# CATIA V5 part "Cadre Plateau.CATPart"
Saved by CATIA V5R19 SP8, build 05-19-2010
Part number: Cadre Plateau
Nomenclature: 5
Bounding box of the stored display mesh (mm): x -294 to 294, y -16.5 to 1531.981, z -105 to 81
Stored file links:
  C:\Users\rphgr\Desktop\0_Tapis_TC520B_vitesse\Cadre Plateau.CATPart
  C:\Program Files\Dassault Systemes\B19\win_b64\reffiles\standard\MetricThickPitch.txt
  D:\Documents\1_Travail\1 - ac-limoges.fr\ac-limoges.fr\Emmanuel Maynard - STI2D_Turgot\3 - Supports\Tapis de course TC520B\Tapis de course TC520B_Ca\0_Tapis_TC520B.CATProduct
  C:\Users\rphgr\Desktop\0_Tapis_TC520B_vitesse\Roulette_Plateau.CATPart
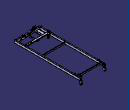
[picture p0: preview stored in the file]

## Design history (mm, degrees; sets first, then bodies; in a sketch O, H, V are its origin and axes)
AxisSystem1: origin (0, 0, 0), X (1, 0, 0), Y (0, 1, 0), Z (0, 0, 1)
Set1
  DatumCurve1: linked copy from another document
Set2
  Sketch1 on YZ plane of AxisSystem1, origin (0, 0, 0), H (0, 1, 0), V (0, 0, 1)
    projected circle E1 centre (1514.5, -85) radius 27.5 from edge of DatumCurve1
Body1 "Cadre" (main body)
  Sketch2 on YZ plane of AxisSystem1, origin (0, 0, 0), H (0, 1, 0), V (0, 0, 1)
    line L1 (12.5, 23.5) -> (12.5, -23.5)
    line L2 (11, -25) -> (-11, -25)
    line L3 (-12.5, -23.5) -> (-12.5, 23.5)
    line L4 (-11, 25) -> (11, 25)
    arc A1 centre (-11, 23.5) radius 1.5 from (-12.5, 23.5) to (-11, 25) cw
    arc A2 centre (11, 23.5) radius 1.5 from (12.5, 23.5) to (11, 25) ccw
    arc A3 centre (11, -23.5) radius 1.5 from (12.5, -23.5) to (11, -25) cw
    arc A4 centre (-11, -23.5) radius 1.5 from (-11, -25) to (-12.5, -23.5) cw
    distance L1 L3 = 25
    distance L4 L2 = 50
    radius A1 = 1.5
    radius A2 = 1.5
    radius A3 = 1.5
    radius A4 = 1.5
    vertical: L1 V, L3 V
    horizontal: L2 H, L4 H
    equidistance: L1 L3 O, L2 L4 O
    tangency: A1 L3, A1 L4, A2 L1, A2 L4, A3 L1, A3 L2, A4 L2, A4 L3
  Pad1: profile Sketch2, direction (1, 0, 0), length 269, mirrored extent, thin wall 1.5
  Sketch3 on ZX plane of AxisSystem1, origin (0, 0, 0), H (0, 0, 1), V (1, 0, 0)
    point P1 (0, 281.5)
    line L1 (25, 292.5) -> (25, 270.5)
    line L2 (23.5, 269) -> (-23.5, 269)
    line L3 (-25, 270.5) -> (-25, 292.5)
    line L4 (-23.5, 294) -> (23.5, 294)
    point P2 (0, -281.5)
    line L5 (25, -270.5) -> (25, -292.5)
    line L6 (23.5, -294) -> (-23.5, -294)
    line L7 (-25, -292.5) -> (-25, -270.5)
    line L8 (-23.5, -269) -> (23.5, -269)
    reference intersected line E1 through (0, 269) direction (-1, 0) from end face of Pad1
    reference intersected line E2 through (0, -269) direction (-1, 0) from start face of Pad1
    reference intersected line E3 (25, 269) -> (25, -269) from face of Pad1
    arc A1 centre (-23.5, -270.5) radius 1.5 from (-25, -270.5) to (-23.5, -269) cw
    arc A2 centre (23.5, -270.5) radius 1.5 from (25, -270.5) to (23.5, -269) ccw
    arc A3 centre (23.5, -292.5) radius 1.5 from (25, -292.5) to (23.5, -294) cw
    arc A4 centre (-23.5, -292.5) radius 1.5 from (-23.5, -294) to (-25, -292.5) cw
    arc A5 centre (-23.5, 292.5) radius 1.5 from (-25, 292.5) to (-23.5, 294) cw
    arc A6 centre (-23.5, 270.5) radius 1.5 from (-23.5, 269) to (-25, 270.5) cw
    arc A7 centre (23.5, 270.5) radius 1.5 from (25, 270.5) to (23.5, 269) cw
    arc A8 centre (23.5, 292.5) radius 1.5 from (25, 292.5) to (23.5, 294) ccw
    distance L4 L2 = 25
    distance L8 L6 = 25
    radius A1 = 1.5
    radius A2 = 1.5
    radius A3 = 1.5
    radius A4 = 1.5
    radius A5 = 1.5
    radius A6 = 1.5
    radius A7 = 1.5
    radius A8 = 1.5
    coincidence: P1 V, P2 V, L1 L5, L2 E1, L8 E2, L1 E3
    vertical: L1 V, L3 V, L5 V, L7 V
    horizontal: L2 H, L4 H, L6 H, L8 H
    equidistance: L1 L3 P1, L2 L4 P1, L5 L7 P2, L6 L8 P2
    tangency: A1 L7, A1 L8, A2 L5, A2 L8, A3 L5, A3 L6, A4 L6, A4 L7, A5 L3, A5 L4, A6 L2, A6 L3, A7 L1, A7 L2, A8 L1, A8 L4
  Pad2: profile Sketch3, direction (0, -1, 0), up to face of Pad1, offset 4, opposite side length 1516.5, thin wall 1.5
  Sketch4 on face of Pad2, origin (-269, 0, 0), H (0, 1, 0), V (0, 0, 1)
    line L1 (179, 3) -> (216, 3)
    line L2 (217.5, 1.5) -> (217.5, -15.5)
    line L3 (216, -17) -> (179, -17)
    line L4 (177.5, -15.5) -> (177.5, 1.5)
    line L5 (589, 10.5) -> (601, 10.5)
    line L6 (602.5, 9) -> (602.5, -18)
    line L7 (601, -19.5) -> (589, -19.5)
    line L8 (587.5, -18) -> (587.5, 9)
    line L9 (1415.1994, 19) -> (1426.8759, 19)
    line L10 (1429, 16.8759) -> (1429, -9.2652)
    line L11 (1427.2652, -11) -> (1415.8517, -11)
    line L12 (1414, -9.1483) -> (1414, 17.8006)
    arc A1 centre (179, -15.5) radius 1.5 from (179, -17) to (177.5, -15.5) cw
    arc A2 centre (179, 1.5) radius 1.5 from (179, 3) to (177.5, 1.5) ccw
    arc A3 centre (216, 1.5) radius 1.5 from (216, 3) to (217.5, 1.5) cw
    arc A4 centre (216, -15.5) radius 1.5 from (217.5, -15.5) to (216, -17) cw
    reference intersected line E1 (12.5, 23.5) -> (12.5, -23.5) from face of Pad1
    reference intersected line E2 through (0, 25) direction (1, 0) from face of Pad2
    arc A5 centre (589, 9) radius 1.5 from (589, 10.5) to (587.5, 9) ccw
    arc A6 centre (601, 9) radius 1.5 from (601, 10.5) to (602.5, 9) cw
    arc A7 centre (601, -18) radius 1.5 from (602.5, -18) to (601, -19.5) cw
    arc A8 centre (589, -18) radius 1.5 from (589, -19.5) to (587.5, -18) cw
    reference intersected line E3 through (0, 25) direction (1, 0) from face of Pad2
    arc A9 centre (1415.1994, 17.8006) radius 1.1994 from (1415.1994, 19) to (1414, 17.8006) ccw
    arc A10 centre (1426.8759, 16.8759) radius 2.1241 from (1426.8759, 19) to (1429, 16.8759) cw
    arc A11 centre (1415.8517, -9.1483) radius 1.8517 from (1415.8517, -11) to (1414, -9.1483) cw
    arc A12 centre (1427.2652, -9.2652) radius 1.7348 from (1429, -9.2652) to (1427.2652, -11) cw
    reference intersected line E4 through (0, 25) direction (1, 0) from face of Pad2
    reference intersected line E5 (1516.5, 23.5) -> (1516.5, -23.5) from start face of Pad2
    distance L1 L3 = 20
    distance L2 L4 = 40
    radius A1 = 1.5
    radius A2 = 1.5
    radius A3 = 1.5
    radius A4 = 1.5
    distance L4 E1 = 165
    distance L1 E2 = 22
    radius A5 = 1.5
    radius A6 = 1.5
    radius A7 = 1.5
    radius A8 = 1.5
    distance L8 L6 = 15
    distance L7 L5 = 30
    distance L8 L2 = 370
    distance L5 E3 = 14.5
    radius A9 = 1.1994
    radius A10 = 2.1241
    radius A11 = 1.8517
    radius A12 = 1.7348
    distance L12 L10 = 15
    distance L11 L9 = 30
    distance L9 E4 = 6
    distance L10 E5 = 87.5
    horizontal: L1 H, L3 H, L5 H, L7 H, L9 H, L11 H
    vertical: L2 V, L4 V, L6 V, L8 V, L10 V, L12 V
    tangency: A1 L3, A1 L4, A2 L1, A2 L4, A3 L1, A3 L2, A4 L2, A4 L3, A5 L5, A5 L8, A6 L5, A6 L6, A7 L6, A7 L7, A8 L7, A8 L8, A9 L9, A9 L12, A10 L9, A10 L10, A11 L11, A11 L12, A12 L10, A12 L11
  Pad3: profile Sketch4, direction (1, 0, 0), up to the existing solid (limit type 2), thin wall 1.5
  Sketch5 on face of Pad3, origin (0, 0, 3), H (1, 0, 0), V (0, 1, 0)
    circle A1 centre (163.8401, 188.5) radius 4.5
    point P1 (163.8401, 188.5)
    circle A2 centre (93.8401, 188.5) radius 4.5
    point P2 (93.8401, 188.5)
    reference intersected line E1 through (0, 217.5) direction (-1, 0) from face of Pad3
    reference intersected line E2 through (0, 217.5) direction (-1, 0) from face of Pad3
    reference projected point E3 (163.8401, 32.5) from axis of face of Hole10
    radius A2 = 4.5
    radius A1 = 4.5
    distance P2 P1 = 70
    distance P1 E1 = 29
    distance P2 E2 = 29
    distance P1 E3 H = 0
  Pocket1: profile Sketch5, direction (0, 0, -1), through (limit type 3)
  Sketch6 on face of Pad2, origin (-281.5, 304.8043, 25), H (1, 0, 0), V (0, 1, 0)
    point P1 (2.5, 18.6957)
    reference intersected line E1 through (-12.5, 0) direction (0, -1) from face of Pad2
    reference intersected line E2 through (0, -321.3043) direction (-1, 0) from end face of Pad2
    distance P1 E1 = 15
    distance P1 E2 = 340
  Hole1: placed by Sketch6, at (-279, 323.5, 25) direction (0, 0, -1), diameter 4.917, depth 5, threaded "M6", thread diameter 6, thread depth 5, pitch 1
  Sketch7 on face of Pad2, origin (-279, 673.206, 25), H (1, 0, 0), V (0, 1, 0)
    point P1 (0, -2.206)
    reference intersected line E1 through (-15, 0) direction (0, -1) from face of Pad2
    reference projected point E2 (0, -349.706) from axis of face of Hole1
    distance P1 E1 = 15
    distance P1 E2 = 347.5
  Hole2: placed by Sketch7, at (-279, 671, 25) direction (0, 0, -1), diameter 4.917, depth 5, threaded "M6", thread diameter 6, thread depth 5, pitch 1
  Sketch8 on face of Pad2, origin (-280.7836, 1023.4299, 25), H (1, 0, 0), V (0, 1, 0)
    point P1 (1.7836, 2.5701)
    reference intersected line E1 through (-13.2164, 0) direction (0, -1) from face of Pad2
    reference projected point E2 (1.7836, -352.4299) from axis of face of Hole2
    distance P1 E1 = 15
    distance P1 E2 = 355
  Hole3: placed by Sketch8, at (-279, 1026, 25) direction (0, 0, -1), diameter 4.917, depth 5, threaded "M6", thread diameter 6, thread depth 5, pitch 1
  Mirror1: of Hole1, Hole2, Hole3, about YZ plane of AxisSystem1
  Plane1: type Offset, RefPlane end face of Pad2, Offset 39
  Sketch9 on Plane1, origin (0, 22.5, 0), H (-1, 0, 0), V (0, 0, 1)
    point P1 (294, 43)
    line L1 (294, 43) -> (294, 28)
    arc A1 centre (291, 28) radius 3 from (294, 28) to (291, 25) cw
    line L2 (291, 25) -> (279, 25)
    point P5 (279, 25)
    reference intersected line E1 (270.5, 25) -> (292.5, 25) from face of Pad2
    reference intersected line E2 (294, 23.5) -> (294, -23.5) from face of Pad2
    radius A1 = 3
    distance P1 L2 = 18
    distance P5 L1 = 15
    vertical: L1 V
    tangency: A1 L1, A1 L2
    horizontal: L2 H
    coincidence: L2 E1, L1 E2
  Pad4: profile Sketch9, direction (0, 1, 0), length 219, thin wall 2
  Sketch10 on face of Pad4, origin (-294, 0, 0), H (0, -1, 0), V (0, 0, 1)
    line L1 (-221.5, 43) -> (-42.5, 43)
    line L2 (-42.5, 43) -> (-42.5, 25)
    line L3 (-42.5, 25) -> (-221.5, 25)
    line L4 (-221.5, 25) -> (-221.5, 43)
    reference intersected line E1 through (0, 25) direction (1, 0) from face of Pad2
    reference intersected line E2 (-241.5, 43) -> (-22.5, 43) from face of Pad4
    reference intersected line E3 (-22.5, 43) -> (-22.5, 28) from start face of Pad4
    reference intersected line E4 (-241.5, 28) -> (-241.5, 43) from end face of Pad4
    distance L2 E3 = 20
    distance L4 E4 = 20
    horizontal: L1 H, L3 H
    vertical: L2 V, L4 V
    coincidence: L3 E1, L1 E2
  Pocket2: profile Sketch10, direction (1, 0, 0), through (limit type 6)
  Sketch11 on face of Pad4, origin (-294, 32.5, 35.5), H (0, 1, 0), V (0, 0, -1)
    point P1 (0, 0.5)
    reference intersected line E1 (10, -7.5) -> (10, 7.5) from face of Pocket2 from Sketch10.L2
    reference intersected line E2 through (0, 10.5) direction (-1, 0) from face of Pad2
    distance P1 E1 = 10
    distance P1 E2 = 10
  Hole4: placed by Sketch11, at (-294, 32.5, 35) direction (1, 0, 0), diameter 3.242, depth 5, threaded "M4", thread diameter 4, thread depth 5, pitch 0.7
  Sketch12 on face of Pad4, origin (-294, 232.5037, 35.5), H (0, 1, 0), V (0, 0, -1)
    point P1 (-1.0037, 0.5)
    reference intersected line E1 (8.9963, 7.5) -> (8.9963, -7.5) from end face of Pad4
    reference intersected line E2 through (0, 10.5) direction (-1, 0) from face of Pad2
    distance P1 E1 = 10
    distance P1 E2 = 10
  Hole5: placed by Sketch12, at (-294, 231.5, 35) direction (1, 0, 0), diameter 3.242, depth 5, threaded "M4", thread diameter 4, thread depth 5, pitch 0.7
  Fillet1: radius 3, on edge [face of Pad4 | end face of Pad4]; edge [face of Pocket2 from Sketch10.L4 | face of Pad4]; edge [face of Pad4 | face of Pocket2 from Sketch10.L2]; edge [start face of Pad4 | face of Pad4]
  Mirror2: of Pad4, Pocket2, Hole4, Hole5, Fillet1, about YZ plane of AxisSystem1
  Sketch13 on face of Pad2, origin (0, 0, -25), H (1, 0, 0), V (0, -1, 0)
    circle A1 centre (-281.5, -40.5) radius 1.75
    point P1 (-281.5, -40.5)
    circle A2 centre (-281.5, -190.5) radius 1.75
    point P2 (-281.5, -190.5)
    circle A3 centre (-281.5, -290.5) radius 1.75
    point P3 (-281.5, -290.5)
    reference intersected line E1 through (-294, 0) direction (0, -1) from face of Pad2
    reference intersected line E2 through (-294, 0) direction (0, -1) from face of Pad2
    reference intersected line E3 through (-294, 0) direction (0, -1) from face of Pad2
    reference intersected line E4 through (0, 16.5) direction (1, 0) from end face of Pad2
    radius A1 = 1.75
    radius A2 = 1.75
    radius A3 = 1.75
    distance P1 E1 = 12.5
    distance P2 E2 = 12.5
    distance P3 E3 = 12.5
    distance P1 E4 = 57
    distance P1 P2 = 150
    distance P2 P3 = 100
  Pocket3: profile Sketch13, direction (0, 0, 1), through (limit type 6)
  Mirror3: of Pocket3, about YZ plane of AxisSystem1
  Sketch14 on YZ plane of AxisSystem1, origin (0, 0, 0), H (0, 1, 0), V (0, 0, 1)
    point P1 (-12.5, 43)
    line L1 (-12.5, 43) -> (-12.5, 28)
    arc A1 centre (-9.5, 28) radius 3 from (-12.5, 28) to (-9.5, 25) ccw
    line L2 (-9.5, 25) -> (2.5, 25)
    point P5 (2.5, 25)
    reference intersected line E1 (-12.5, -23.5) -> (-12.5, 23.5) from face of Pad1
    reference intersected line E2 (-11, 25) -> (11, 25) from face of Pad1
    radius A1 = 3
    distance P1 L2 = 18
    distance P5 L1 = 15
    vertical: L1 V
    tangency: A1 L1, A1 L2
    horizontal: L2 H
    coincidence: L1 E1, L2 E2
  Pad5: profile Sketch14, direction (1, 0, 0), length 120, mirrored extent, thin wall 2
  Sketch15 on face of Pad5, origin (0, -12.5, 0), H (1, 0, 0), V (0, 0, 1)
    line L1 (-100, 43) -> (100, 43)
    line L2 (100, 43) -> (100, 25)
    line L3 (100, 25) -> (-100, 25)
    line L4 (-100, 25) -> (-100, 43)
    reference intersected line E1 (-120, 43) -> (120, 43) from face of Pad5
    reference intersected line E2 through (0, 25) direction (1, 0) from face of Pad1
    reference intersected line E3 (120, 43) -> (120, 28) from end face of Pad5
    reference intersected line E4 (-120, 28) -> (-120, 43) from start face of Pad5
    distance L2 E3 = 20
    distance L4 E4 = 20
    horizontal: L1 H, L3 H
    vertical: L2 V, L4 V
    coincidence: L1 E1, L3 E2
  Pocket4: profile Sketch15, direction (0, 1, 0), through (limit type 3)
  Fillet2: radius 3, on edge [start face of Pad5 | face of Pad5]; edge [face of Pocket4 from Sketch15.L4 | face of Pad5]; edge [face of Pad5 | face of Pocket4 from Sketch15.L2]; edge [face of Pad5 | end face of Pad5]
  Sketch16 on face of Pad5, origin (-110, -12.5, 35.5), H (1, 0, 0), V (0, 0, 1)
    point P1 (0, -0.5)
    reference intersected line E1 (-10, -7.5) -> (-10, 7.5) from start face of Pad5
    reference intersected line E2 through (0, -10.5) direction (1, 0) from face of Pad1
    distance P1 E1 = 10
    distance P1 E2 = 10
  Hole6: placed by Sketch16, at (-110, -12.5, 35) direction (0, 1, 0), diameter 3.242, depth 5, threaded "M4", thread diameter 4, thread depth 5, pitch 0.7
  Sketch17 on face of Pad5, origin (110, -12.5, 35.5), H (1, 0, 0), V (0, 0, 1)
    point P1 (0, -0.5)
    reference intersected line E1 (-10, 7.5) -> (-10, -7.5) from face of Pocket4 from Sketch15.L2
    reference intersected line E2 through (0, -10.5) direction (1, 0) from face of Pad1
    distance P1 E1 = 10
    distance P1 E2 = 10
  Hole7: placed by Sketch17, at (110, -12.5, 35) direction (0, 1, 0), diameter 3.242, depth 5, threaded "M4", thread diameter 4, thread depth 5, pitch 0.7
  Sketch18 on face of Pad3, origin (0, 177.5, 0), H (1, 0, 0), V (0, 0, 1)
    line L1 (1.5, 6) -> (11.5, 6)
    line L2 (13, 4.5) -> (13, -18.5)
    line L3 (11.5, -20) -> (1.5, -20)
    line L4 (0, -18.5) -> (0, 4.5)
    arc A1 centre (1.5, 4.5) radius 1.5 from (1.5, 6) to (0, 4.5) ccw
    arc A2 centre (11.5, 4.5) radius 1.5 from (13, 4.5) to (11.5, 6) ccw
    arc A3 centre (11.5, -18.5) radius 1.5 from (13, -18.5) to (11.5, -20) cw
    arc A4 centre (1.5, -18.5) radius 1.5 from (1.5, -20) to (0, -18.5) cw
    reference intersected line E1 through (0, 3) direction (1, 0) from face of Pad3
    reference intersected line E2 (269, -23.5) -> (269, 23.5) from face of Pad2
    radius A1 = 1.5
    radius A2 = 1.5
    radius A3 = 1.5
    radius A4 = 1.5
    distance L2 L4 = 13
    distance L3 L1 = 26
    distance L1 E1 = 3
    distance E2 L2 = 256
    horizontal: L1 H, L3 H
    vertical: L2 V, L4 V
    tangency: A1 L1, A1 L4, A2 L2, A2 L1, A3 L2, A3 L3, A4 L3, A4 L4
  Pad6: profile Sketch18, direction (0, -1, 0), up to face of Pad1
  Plane2: type Offset, RefPlane YZ plane of AxisSystem1, Offset 17, reversed
  Sketch19 on Plane2, origin (-17, 0, 0), H (0, 1, 0), V (0, 0, 1)
    line L1 (12.5, 25) -> (-7.5, 25)
    line L2 (-7.5, 25) -> (-7.5, 31)
    arc A1 centre (42.5, 31) radius 50 from (-7.5, 31) to (42.5, 81) cw
    point P5 (42.5, 81)
    construction line L3 (57.5, 66) -> (44.5614, 66)
    point P6 (57.5, 66)
    line L4 (57.5, 51) -> (47.5, 51)
    line L5 (42.5, 81) -> (57.5, 81)
    arc A2 centre (57.5, 66) radius 15 from (57.5, 81) to (57.5, 51) cw
    point P9 (42.5, 81)
    line L6 (12.5, 25) -> (12.5, -25)
    line L7 (12.5, -25) -> (27.5, -25)
    line L8 (27.5, -25) -> (27.5, 31)
    arc A3 centre (47.5, 31) radius 20 from (27.5, 31) to (47.5, 51) cw
    reference intersected line E1 (-11, 25) -> (11, 25) from face of Pad1
    reference intersected line E2 (12.5, 23.5) -> (12.5, -23.5) from face of Pad1
    reference intersected line E3 (11, -25) -> (-11, -25) from face of Pad1
    circle A4 centre (57.5, 66) radius 5.2
    distance L3 L4 = 15
    distance L2 L8 = 35
    distance L2 L6 = 20
    distance P6 L6 = 45
    distance L1 L3 = 41
    radius A1 = 50
    radius A3 = 20
    radius A4 = 5.2
    horizontal: L1 H, L3 H, L7 H
    vertical: L2 V, L6 V, L8 V
    tangency: A1 L2, A2 L4, A2 L5, A3 L8, L4 A3, A1 L5
    coincidence: P9 P5, L1 E1, L6 E2, L7 E3
    parallelism: L5 L4
  Pad7: profile Sketch19, direction (-1, 0, 0), length 4
  RectPattern1: of Pad7, direction 1 instances 2, spacing 29, along edge [XY plane of AxisSystem1 | ZX plane of AxisSystem1] reversed
  Sketch20 on face of Pad3, origin (0, 177.5, 0), H (-1, 0, 0), V (0, 0, 1)
    point P1 (142, 3)
    line L1 (143.5, 3) -> (166.5, 3)
    line L2 (168, 1.5) -> (168, -8.5)
    line L3 (166.5, -10) -> (143.5, -10)
    line L4 (142, -8.5) -> (142, 1.5)
    arc A1 centre (143.5, 1.5) radius 1.5 from (143.5, 3) to (142, 1.5) ccw
    arc A2 centre (143.5, -8.5) radius 1.5 from (143.5, -10) to (142, -8.5) cw
    arc A3 centre (166.5, -8.5) radius 1.5 from (168, -8.5) to (166.5, -10) cw
    arc A4 centre (166.5, 1.5) radius 1.5 from (166.5, 3) to (168, 1.5) cw
    reference intersected line E1 through (0, 3) direction (1, 0) from face of Pad3
    reference intersected line E2 (0, 4.5) -> (0, -18.5) from face of Pad6 from Sketch18.L4
    radius A1 = 1.5
    radius A2 = 1.5
    radius A3 = 1.5
    radius A4 = 1.5
    distance L1 L3 = 13
    distance L4 L2 = 26
    distance L4 E2 = 142
    horizontal: L1 H, L3 H
    vertical: L2 V, L4 V
    coincidence: L1 P1, L4 P1, L1 E1
    tangency: A1 L1, A1 L4, A2 L3, A2 L4, A3 L2, A3 L3, A4 L1, A4 L2
  Pad8: profile Sketch20, direction (0, 1, 0), up to face of Pad1
  Sketch21 on face of Pad1, origin (0, 12.5, 0), H (-1, 0, 0), V (0, 0, 1)
    line L1 (189, -13) -> (244, -13)
    line L2 (244, -13) -> (244, -15)
    line L3 (244, -15) -> (189, -15)
    line L4 (189, -15) -> (189, -13)
    reference intersected line E1 through (0, 25) direction (1, 0) from face of Pad1
    reference intersected line E2 (269, -23.5) -> (269, 23.5) from face of Pad2
    distance L1 L3 = 2
    distance L4 L2 = 55
    distance L1 E1 = 38
    distance L2 E2 = 25
    horizontal: L1 H, L3 H
    vertical: L2 V, L4 V
  Pad9: profile Sketch21, direction (0, 1, 0), up to face of Pad3
Body2
  Plane3: type Offset, RefPlane face of Pad2, Offset 20
  Sketch22 on Plane3, origin (0, 0, -5), H (1, 0, 0), V (0, 1, 0)
    point P1 (-280, 217.5)
    line L1 (-280, 217.5) -> (-234, 217.5)
    arc A1 centre (-234, 223.5) radius 6 from (-234, 217.5) to (-228, 223.5) ccw
    line L2 (-228, 223.5) -> (-228, 249.5)
    arc A2 centre (-234, 249.5) radius 6 from (-228, 249.5) to (-234, 255.5) ccw
    line L3 (-234, 255.5) -> (-280, 255.5)
    point P8 (-280, 255.5)
    reference intersected line E1 (-269, 217.5) -> (269, 217.5) from face of Pad3
    reference intersected line E2 (-269, 1516.5) -> (-269, -16.5) from face of Pad2
    reference intersected line E3 (-269, 1516.5) -> (-269, -16.5) from face of Pad2
    reference intersected line E4 (-269, 1516.5) -> (-269, -16.5) from face of Pad2
    radius A1 = 6
    distance L2 E2 = 41
    distance P8 E3 = 11
    distance P1 E4 = 11
    distance L3 L1 = 38
    radius A2 = 6
    horizontal: L1 H, L3 H
    tangency: A1 L1, L2 A1, A2 L2, A2 L3
    coincidence: L1 E1
  Pad10: profile Sketch22, direction (0, 0, -1), length 70, thin wall 4
  Sketch23 on face of Pad10, origin (0, 255.5, 0), H (-1, 0, 0), V (0, 0, 1)
    line L1 (281.8055, -34) -> (257.1193, -34)
    arc A1 centre (257.1193, -43.3989) radius 9.3989 from (257.1193, -34) to (250.196, -37.0422) ccw
    line L2 (250.196, -37.0422) -> (240, -75.0943)
    point P5 (240, -75.0943)
    reference intersected line E1 through (228, 0) direction (0, 1) from face of Pad10
    reference intersected line E2 through (228, 0) direction (0, 1) from face of Pad10
    line L3 (281.8055, -34) -> (281.8055, -75.0943)
    line L4 (281.8055, -75.0943) -> (240, -75.0943)
    projected line E3 (270.5, 25) -> (292.5, 25) from edge [start face of Pad2 | face of Pad2]
    projected arc E4 centre (270.5, 23.5) radius 1.5 from (270.5, 25) to (269, 23.5) ccw from edge [face of Pad2 | start face of Pad2]
    projected line E5 (269, -23.5) -> (269, 23.5) from edge [start face of Pad2 | face of Pad2]
    projected arc E6 centre (270.5, -23.5) radius 1.5 from (269, -23.5) to (270.5, -25) ccw from edge [face of Pad2 | start face of Pad2]
    projected line E7 (292.5, -25) -> (270.5, -25) from edge [start face of Pad2 | face of Pad2]
    projected arc E8 centre (292.5, -23.5) radius 1.5 from (292.5, -25) to (294, -23.5) ccw from edge [face of Pad2 | start face of Pad2]
    projected line E9 (294, 23.5) -> (294, -23.5) from edge [start face of Pad2 | face of Pad2]
    projected arc E10 centre (292.5, 23.5) radius 1.5 from (294, 23.5) to (292.5, 25) ccw from edge [face of Pad2 | start face of Pad2]
    distance E1 P5 = 12
    angle L2 E2 = 15
    horizontal: L1 H, L4 H
    tangency: A1 L1
    vertical: L3 V
  Pocket5: profile Sketch23, direction (0, -1, 0), through (limit type 3)
  Sketch24 on face of Pad10, origin (-228, 0, 0), H (0, 1, 0), V (0, 0, 1)
    circle A1 centre (236.5, -62.5) radius 6.25
    point P1 (236.5, -62.5)
    reference intersected line E1 through (255.5, 0) direction (0, -1) from face of Pad10
    reference intersected line E2 (249.5, -75) -> (223.5, -75) from end face of Pad10
    radius A1 = 6.25
    distance P1 E1 = 19
    distance P1 E2 = 12.5
  Pocket6: profile Sketch24, direction (-1, 0, 0), through (limit type 3)
  Mirror4: of the body so far, about YZ plane of AxisSystem1
Body3
  Plane4: type Offset, RefPlane face of Pad2, Offset 35
  Sketch25 on Plane4, origin (0, 0, 10), H (1, 0, 0), V (0, 1, 0)
    point P1 (-279, 1429)
    line L1 (-279, 1429) -> (-247.5, 1429)
    arc A1 centre (-247.5, 1433) radius 4 from (-247.5, 1429) to (-243.5, 1433) ccw
    line L2 (-243.5, 1433) -> (-243.5, 1500)
    arc A2 centre (-247.5, 1500) radius 4 from (-243.5, 1500) to (-247.5, 1504) ccw
    line L3 (-247.5, 1504) -> (-279, 1504)
    point P8 (-279, 1504)
    reference intersected line E1 (-269, 1429) -> (269, 1429) from face of Pad3
    reference projected line E2 (-269, 1516.5) -> (-269, -16.5) from edge [face of Pad2 | face of Pad2]
    reference intersected line E3 (-269, 1516.5) -> (-269, -16.5) from face of Pad2
    reference intersected line E4 (-269, 1516.5) -> (-269, -16.5) from face of Pad2
    distance P1 E2 = 10
    distance P8 E3 = 10
    radius A1 = 4
    radius A2 = 4
    distance L3 L1 = 75
    distance L2 E4 = 25.5
    horizontal: L1 H
    tangency: A1 L1, L2 A1, A2 L2, L3 A2
    coincidence: L1 E1
  Pad11: profile Sketch25, direction (0, 0, 1), length 45, thin wall 3
  Sketch26 on face of Pad11, origin (0, 1504, 0), H (-1, 0, 0), V (0, 0, 1)
    projected line E1 (269, -23.5) -> (269, 23.5) from edge [start face of Pad2 | face of Pad2]
    projected arc E2 centre (270.5, 23.5) radius 1.5 from (270.5, 25) to (269, 23.5) ccw from edge [face of Pad2 | start face of Pad2]
    projected line E3 (270.5, 25) -> (292.5, 25) from edge [start face of Pad2 | face of Pad2]
  Pocket7: profile Sketch26, direction (0, -1, 0), through (limit type 6)
  Sketch27 on face of Pad11, origin (0, 1504, 0), H (-1, 0, 0), V (0, 0, 1)
    line L1 (251.3626, 67.6374) -> (279, 40)
    point P2 (279, 40)
    reference intersected line E1 (270.5, 25) -> (292.5, 25) from face of Pad2
    reference intersected line E2 (279, 55) -> (279, 10) from face of Pad11
    reference intersected line E3 (270.5, 25) -> (292.5, 25) from face of Pad2
    angle L1 E1 = 45
    distance P2 E3 = 15
    coincidence: P2 E2
  Pocket8: profile Sketch27, direction (0, -1, 0), through (limit type 6)
  Sketch28 on face of Pad11, origin (0, 1504, 0), H (-1, 0, 0), V (0, 0, 1)
    circle A1 centre (256.75, 45) radius 4.5
    point P1 (256.75, 45)
    reference intersected line E1 (247.5, 55) -> (279, 55) from end face of Pad11
    reference intersected line E2 through (243.5, 0) direction (0, -1) from face of Pad11
    radius A1 = 4.5
    distance P1 E1 = 10
    distance P1 E2 = 13.25
  Pocket9: profile Sketch28, direction (0, -1, 0), through (limit type 3)
  Sketch29 on face of Pad11, origin (-243.5, 0, 0), H (0, 1, 0), V (0, 0, 1)
    line L1 (1436.5, 60.4755) -> (1496.5, 60.4755)
    line L2 (1496.5, 60.4755) -> (1496.5, 39)
    line L3 (1492.5, 35) -> (1440.5, 35)
    line L4 (1436.5, 39) -> (1436.5, 60.4755)
    arc A1 centre (1440.5, 39) radius 4 from (1440.5, 35) to (1436.5, 39) cw
    arc A2 centre (1492.5, 39) radius 4 from (1492.5, 35) to (1496.5, 39) ccw
    reference intersected line E1 (1433, 55) -> (1500, 55) from end face of Pad11
    reference intersected line E2 through (1429, 0) direction (0, -1) from face of Pad11
    radius A1 = 4
    radius A2 = 4
    distance L4 L2 = 60
    distance L3 E1 = 20
    distance L4 E2 = 7.5
    horizontal: L1 H, L3 H
    vertical: L2 V, L4 V
    tangency: A1 L3, A1 L4, A2 L3, A2 L2
  Pocket10: profile Sketch29, direction (-1, 0, 0), through (limit type 3)
  Sketch30 on face of Pad11, origin (0, 1504, 0), H (-1, 0, 0), V (0, 0, 1)
    circle A1 centre (254, 18) radius 1.75
    point P1 (254, 18)
    reference intersected line E1 (247.5, 55) -> (279, 55) from end face of Pad11
    reference intersected line E2 (269, -23.5) -> (269, 23.5) from face of Pad2
    radius A1 = 1.75
    distance P1 E1 = 37
    distance P1 E2 = 15
  Pocket11: profile Sketch30, direction (0, -1, 0), through (limit type 6)
  Mirror5: of the body so far, about YZ plane of AxisSystem1
Body4
  Sketch31 on face of Pad2, origin (-269, 0, 0), H (0, 1, 0), V (0, 0, 1)
    line L1 (1368, 45) -> (1384, 45)
    line L2 (1386.5, 42.5) -> (1386.5, 25)
    line L3 (1365.5, 25) -> (1365.5, 42.5)
    point P1 (1386.5, 25)
    point P2 (1365.5, 25)
    arc A1 centre (1368, 42.5) radius 2.5 from (1368, 45) to (1365.5, 42.5) ccw
    arc A2 centre (1384, 42.5) radius 2.5 from (1384, 45) to (1386.5, 42.5) cw
    reference intersected line E1 through (0, 25) direction (1, 0) from face of Pad2
    reference intersected line E2 through (0, 25) direction (1, 0) from face of Pad2
    reference intersected line E3 through (0, 25) direction (1, 0) from face of Pad2
    axis line L4 (1376, 45) -> (1376, 41.4394)
    point P9 (1376, 45)
    reference projected line E4 through (1026, 0) direction (0, -1) from axis of face of Hole3
    radius A1 = 2.5
    radius A2 = 2.5
    distance L1 E3 = 20
    distance L2 L3 = 21
    distance L4 E4 = 350
    horizontal: L1 H
    vertical: L2 V, L3 V, L4 V
    tangency: A1 L1, A1 L3, A2 L1, A2 L2
    coincidence: P2 E1, P1 E2
    midpoint: P9 L1
  Pad12: profile Sketch31, direction (-1, 0, 0), length 18, thin wall 2
  Sketch32 on face of Pad12, origin (-278, 1376, 45), H (1, 0, 0), V (0, 1, 0)
    point P1 (0, 0)
    reference intersected line E1 (9, 8) -> (9, -8) from start face of Pad12
    reference intersected line E2 through (0, -10.5) direction (-1, 0) from face of Pad12
    distance E1 P1 = 9
    distance P1 E2 = 10.5
  Hole8: placed by Sketch32, at (-278, 1376, 45) direction (0, 0, -1), diameter 4.917, depth 5, threaded "M6", thread diameter 6, thread depth 5, pitch 1
  Mirror6: of the body so far, about YZ plane of AxisSystem1
Body5
  Sketch33 on start face of Pad2, origin (0, 1516.5, 0), H (-1, 0, 0), V (0, 0, 1)
    point P1 (287.5, -105)
    line L1 (287.5, -105) -> (287.5, -27.5)
    arc A1 centre (285, -27.5) radius 2.5 from (287.5, -27.5) to (285, -25) ccw
    line L2 (285, -25) -> (260, -25)
    arc A2 centre (260, -27.5) radius 2.5 from (260, -25) to (257.5, -27.5) ccw
    line L3 (257.5, -27.5) -> (257.5, -105)
    point P8 (257.5, -105)
    reference intersected line E1 (292.5, -25) -> (270.5, -25) from face of Pad2
    reference intersected line E2 (294, 23.5) -> (294, -23.5) from face of Pad2
    distance P1 L2 = 80
    distance P8 L2 = 80
    radius A1 = 2.5
    radius A2 = 2.5
    distance L1 L3 = 30
    distance L1 E2 = 6.5
    vertical: L1 V
    tangency: A1 L1, L2 A1, A2 L2, L3 A2
    coincidence: L2 E1
  Pad13: profile Sketch33, direction (0, -1, 0), length 28, opposite side length 20, thin wall 2.5
  Sketch34 on face of Pad13, origin (-287.5, 0, 0), H (0, -1, 0), V (0, 0, 1)
    circle A1 centre (-1514.5, -93) radius 4.2
    point P1 (-1514.5, -93)
    reference intersected line E1 (16.5, -25) -> (-1516.5, -25) from face of Pad2
    reference intersected line E2 through (-1516.5, 0) direction (0, -1) from start face of Pad2
    radius A1 = 4.2
    distance P1 E1 = 68
    distance P1 E2 = 2
  Pocket12: profile Sketch34, direction (1, 0, 0), through (limit type 3)
  Sketch35 on face of Pad13, origin (-287.5, 0, 0), H (0, -1, 0), V (0, 0, 1)
    arc A1 centre (-1514.5, -93) radius 17.5 from (-1531.9814, -92.1941) to (-1497.0186, -93.8059) ccw
    reference projected point E1 (-1514.5, -93) from axis of face of Pocket12 from Sketch34.A1
    arc A2 centre (-1047.496, -114.5291) radius 450 from (-1488.5, -25) to (-1497.0186, -93.8059) ccw
    arc A3 centre (-1047.496, -114.5291) radius 485 from (-1524.161, -25) to (-1531.9814, -92.1941) ccw
    point P3 (-1047.496, -114.5291)
    line L1 (-1524.161, -25) -> (-1488.5, -25)
    point P5 (-1488.5, -25)
    reference intersected line E2 through (0, -25) direction (1, 0) from face of Pad13
    reference intersected line E3 (-1488.5, -27.5) -> (-1488.5, -105) from end face of Pad13
    radius A1 = 17.5
    radius A2 = 450
    concentricity: A1 E1, P3 A2
    tangency: A2 A1, A3 A1
    horizontal: L1 H
    coincidence: L1 E2, P5 E3
  Pocket13: profile Sketch35, direction (1, 0, 0), through (limit type 3), outer side
  Mirror7: of the body so far, about YZ plane of AxisSystem1
Body6
  Sketch36 on face of Pad3, origin (0, 0, 3), H (1, 0, 0), V (0, 1, 0)
    line L1 (-247, 211.5) -> (-266, 211.5)
    line L2 (-269, 214.5) -> (-269, 258.5)
    line L3 (-266, 261.5) -> (-247, 261.5)
    line L4 (-244, 258.5) -> (-244, 214.5)
    arc A1 centre (-247, 214.5) radius 3 from (-247, 211.5) to (-244, 214.5) ccw
    arc A2 centre (-266, 214.5) radius 3 from (-266, 211.5) to (-269, 214.5) cw
    arc A3 centre (-266, 258.5) radius 3 from (-269, 258.5) to (-266, 261.5) cw
    arc A4 centre (-247, 258.5) radius 3 from (-247, 261.5) to (-244, 258.5) cw
    reference intersected line E1 (-269, 1516.5) -> (-269, -16.5) from face of Pad2
    reference intersected line E2 through (0, 177.5) direction (1, 0) from face of Pad3
    radius A1 = 3
    radius A2 = 3
    radius A3 = 3
    radius A4 = 3
    distance L4 L2 = 25
    distance L3 L1 = 50
    distance L1 E2 = 34
    horizontal: L1 H, L3 H
    vertical: L2 V, L4 V
    tangency: A1 L1, A1 L4, A2 L1, A2 L2, A3 L2, A3 L3, A4 L3, A4 L4
    coincidence: L2 E1
  Pad14: profile Sketch36, direction (0, 0, 1), length 55, thin wall 1.5
  Sketch37 on face of Pad14, origin (0, 261.5, 0), H (-1, 0, 0), V (0, 0, 1)
    circle A1 centre (256.5, 45) radius 4.5
    point P1 (256.5, 45)
    reference intersected line E1 through (244, 0) direction (0, 1) from face of Pad14
    reference intersected line E2 (270.5, 25) -> (292.5, 25) from face of Pad2
    radius A1 = 4.5
    distance P1 E1 = 12.5
    distance P1 E2 = 20
  Pocket14: profile Sketch37, direction (0, -1, 0), through (limit type 3)
  Sketch38 on face of Pad14, origin (-244, 0, 0), H (0, 1, 0), V (0, 0, 1)
    construction line L1 (229.5, 45) -> (244.5, 45)
    point P2 (244.5, 45)
    line L2 (244.5, 37.5) -> (229.5, 37.5)
    arc A1 centre (244.5, 45) radius 7.5 from (246, 52.3485) to (244.5, 37.5) cw
    arc A2 centre (229.5, 45) radius 7.5 from (229.5, 37.5) to (228, 52.3485) cw
    point P5 (237, 45)
    line L3 (228, 58) -> (246, 58)
    line L4 (246, 58) -> (246, 52.3485)
    line L5 (228, 52.3485) -> (228, 58)
    reference intersected line E1 (214.5, 58) -> (258.5, 58) from end face of Pad14
    reference intersected line E2 through (0, 25) direction (1, 0) from face of Pad2
    reference intersected line E3 through (1432, 0) direction (0, -1) from face of Pad11
    distance A2 A1 = 30
    distance L5 L4 = 18
    radius A1 = 7.5
    distance L1 E2 = 20
    distance L4 P2 = 1.5
    radius A2 = 7.5
    distance P5 E3 = 1195
    horizontal: L1 H, L3 H
    tangency: A1 L2, A2 L2
    midpoint: P5 L1
    vertical: L4 V, L5 V
    coincidence: L3 E1
  Pocket15: profile Sketch38, direction (-1, 0, 0), through (limit type 6)
  Fillet3: radius 1, on edge [face of Pocket15 from Sketch38.A2 | face of Pocket15 from Sketch38.L5]; edge [face of Pocket15 from Sketch38.L4 | face of Pocket15 from Sketch38.A1]; edge [end face of Pad14 | face of Pocket15 from Sketch38.L4]; edge [face of Pocket15 from Sketch38.L5 | end face of Pad14]
  Sketch39 on face of Pad2, origin (269, 0, 0), H (0, -1, 0), V (0, 0, 1)
    line L1 (-264.5, 59.5) -> (-224.5, 59.5)
    line L2 (-224.5, 59.5) -> (-224.5, -0.5)
    line L3 (-224.5, -0.5) -> (-264.5, -0.5)
    line L4 (-264.5, -0.5) -> (-264.5, 59.5)
    circle A1 centre (-244.5, 45) radius 7.7
    point P5 (-244.5, 45)
    reference intersected line E1 through (0, 25) direction (1, 0) from face of Pad2
    reference intersected line E2 through (0, 25) direction (1, 0) from face of Pad2
    reference projected point E3 (-244.5, 45) from axis of face of Pocket15 from Sketch38.A1
    reference projected point E4 (-229.5, 45) from axis of face of Pocket15 from Sketch38.A2
    radius A1 = 7.7
    distance P5 L4 = 20
    distance P5 E1 = 20
    distance L4 L2 = 40
    distance L1 L3 = 60
    distance L1 E2 = 34.5
    horizontal: L1 H, L3 H
    vertical: L2 V, L4 V
    equidistance: P5 E3 E4
  Pad15: profile Sketch39, direction (-1, 0, 0), length 4
  Fillet4: radius 3, on edge [face of Pad15 from Sketch39.L4 | face of Pad15 from Sketch39.L1]; edge [face of Pad15 from Sketch39.L1 | face of Pad15 from Sketch39.L2]
Body7
  Sketch40 on face of Pad3, origin (0, 0, 3), H (1, 0, 0), V (0, 1, 0)
    point P1 (0, 269.5351)
    line L1 (19, 249.5) -> (19, 220.5)
    line L2 (16, 217.5) -> (-16, 217.5)
    line L3 (-19, 220.5) -> (-19, 249.5)
    point P2 (19, 249.5)
    point P3 (-19, 249.5)
    arc A1 centre (-16, 220.5) radius 3 from (-16, 217.5) to (-19, 220.5) cw
    arc A2 centre (16, 220.5) radius 3 from (19, 220.5) to (16, 217.5) cw
    reference intersected line E1 through (0, 0) direction (0, 1) from YZ plane of AxisSystem1
    reference intersected line E2 through (0, 217.5) direction (-1, 0) from face of Pad3
    radius A1 = 3
    radius A2 = 3
    distance L1 L3 = 38
    distance P2 L2 = 32
    distance P3 L2 = 32
    coincidence: P1 V, P1 E1, L2 E2
    vertical: L1 V, L3 V
    horizontal: L2 H
    equidistance: L1 L3 P1
    tangency: A1 L2, A1 L3, A2 L1, A2 L2
  Pad16: profile Sketch40, direction (0, 0, 1), up to face of Pad3, thin wall 3
  Sketch41 on face of Pad16, origin (-19, 0, 0), H (0, -1, 0), V (0, 0, 1)
    circle A1 centre (-239.5, -7) radius 4.2
    point P1 (-239.5, -7)
    reference intersected line E1 (-249.5, 3) -> (-220.5, 3) from start face of Pad16
    reference intersected line E2 (-249.5, -17) -> (-249.5, 3) from face of Pad16
    radius A1 = 4.2
    distance P1 E1 = 10
    distance P1 E2 = 10
  Pocket16: profile Sketch41, direction (1, 0, 0), through (limit type 3)
  Fillet5: radius 10, on edge [face of Pad16 | start face of Pad16] (x2); edge [end face of Pad16 | face of Pad16] (x2)
Body8
  Sketch42 on face of Pad3, origin (0, 217.5, 0), H (-1, 0, 0), V (0, 0, 1)
    line L1 (-163.8401, 24) -> (-123.8401, 24)
    line L2 (-123.8401, 24) -> (-123.8401, -16)
    line L3 (-123.8401, -16) -> (-163.8401, -16)
    line L4 (-163.8401, -16) -> (-163.8401, 24)
    reference intersected line E1 through (0, 3) direction (1, 0) from face of Pad3
    reference projected line E2 through (-163.8401, 0) direction (0, 1) from axis of face of Pocket1 from Sketch5.A1
    distance L3 L1 = 40
    distance L2 L4 = 40
    distance L1 E1 = 21
    horizontal: L1 H, L3 H
    vertical: L2 V, L4 V
    coincidence: L4 E2
  Pad17: profile Sketch42, direction (0, 1, 0), length 4
  Fillet6: radius 5, on edge [face of Pad17 from Sketch42.L1 | face of Pad17 from Sketch42.L2]; edge [face of Pad17 from Sketch42.L2 | face of Pad17 from Sketch42.L3]; edge [face of Pad17 from Sketch42.L3 | face of Pad17 from Sketch42.L4]; edge [face of Pad17 from Sketch42.L4 | face of Pad17 from Sketch42.L1]
Body9
  Sketch43 on face of Pad1, origin (0, 12.5, 0), H (-1, 0, 0), V (0, 0, 1)
    point P1 (-183.8401, 37)
    line L1 (-183.8401, 37) -> (-183.8401, 5)
    line L2 (-180.8401, 2) -> (-76.8401, 2)
    line L3 (-73.8401, 5) -> (-73.8401, 37)
    point P2 (-73.8401, 37)
    arc A1 centre (-180.8401, 5) radius 3 from (-183.8401, 5) to (-180.8401, 2) ccw
    arc A2 centre (-76.8401, 5) radius 3 from (-76.8401, 2) to (-73.8401, 5) ccw
    reference intersected line E1 through (0, 25) direction (1, 0) from face of Pad1
    reference intersected line E2 (-269, 23.5) -> (-269, -23.5) from face of Pad2
    radius A1 = 3
    radius A2 = 3
    distance L1 L3 = 110
    distance P1 L2 = 35
    distance P2 L2 = 35
    distance L2 E1 = 23
    distance L1 E2 = 85.1599
    vertical: L1 V, L3 V
    horizontal: L2 H
    tangency: A1 L1, A1 L2, A2 L2, A2 L3
  Pad18: profile Sketch43, direction (0, 1, 0), length 35, thin wall 4
  Sketch44 on face of Pad18, origin (73.8401, 0, 0), H (0, -1, 0), V (0, 0, 1)
    line L1 (-22.5, 37) -> (-47.5, 6)
    point P1 (-22.5, 37)
    point P2 (-47.5, 6)
    reference projected line E1 (-47.5, 5) -> (-47.5, 37) from edge [face of Pad18 | end face of Pad18]
    reference projected point E2 (-47.5, 6) from edge [end face of Pad18 | face of Pad18]
    reference intersected line E3 (-47.5, 37) -> (-12.5, 37) from face of Pad18
    reference projected line E4 (-12.5, 5) -> (-12.5, 37) from edge [start face of Pad18 | face of Pad18]
    distance P1 E4 = 10
    coincidence: P2 E1, P2 E2, P1 E3
  Pocket17: profile Sketch44, direction (1, 0, 0), through (limit type 3)
  Sketch45 on face of Pad18, origin (116.824, 25.3732, 6), H (1, 0, 0), V (0, 1, 0)
    point P1 (-22.9838, 7.1268)
    reference intersected line E1 (-385.824, -12.8732) -> (152.176, -12.8732) from face of Pad1
    reference intersected line E2 (-38.9838, 22.1268) -> (-38.9838, -12.8732) from face of Pad18
    distance P1 E1 = 20
    distance E2 P1 = 16
  Hole9: placed by Sketch45, at (93.8401, 32.5, 6) direction (0, 0, -1), diameter 6.647, through (limit type 3), threaded "M8", thread diameter 8, thread depth 4, pitch 1.25
  Sketch46 on face of Pad18, origin (161.2348, 33.0815, 6), H (1, 0, 0), V (0, 1, 0)
    point P1 (2.6053, -0.5815)
    reference intersected line E1 (-430.2348, -20.5815) -> (107.7652, -20.5815) from face of Pad1
    reference projected point E2 (-67.3947, -0.5815) from axis of face of Hole9
    distance P1 E1 = 20
    distance P1 E2 = 70
  Hole10: placed by Sketch46, at (163.8401, 32.5, 6) direction (0, 0, -1), diameter 6.647, through (limit type 3), threaded "M8", thread diameter 8, thread depth 4, pitch 1.25
Body10
  Sketch47 on face of Pad3, origin (0, 0, -17), H (1, 0, 0), V (0, -1, 0)
    point P1 (93.8401, -188.5)
    point P2 (97.8816, -195.5)
    point P3 (101.9231, -188.5)
    point P4 (97.8816, -181.5)
    point P5 (89.7987, -181.5)
    point P6 (85.7572, -188.5)
    point P7 (89.7987, -195.5)
    point P8 (99.9023, -192)
    line L1 (97.8816, -195.5) -> (101.9231, -188.5)
    line L2 (101.9231, -188.5) -> (97.8816, -181.5)
    line L3 (97.8816, -181.5) -> (89.7987, -181.5)
    line L4 (89.7987, -181.5) -> (85.7572, -188.5)
    line L5 (85.7572, -188.5) -> (89.7987, -195.5)
    line L6 (89.7987, -195.5) -> (97.8816, -195.5)
    construction line L7 (93.8401, -188.5) -> (99.9023, -192)
    construction circle A1 centre (93.8401, -188.5) radius 8.0829
    construction arc A2 centre (85.7572, -188.5) radius 8.0829 from (89.7987, -181.5) to (89.7987, -195.5) cw
    construction arc A3 centre (101.9231, -188.5) radius 8.0829 from (97.8816, -181.5) to (97.8816, -195.5) ccw
    point P9 (163.8401, -188.5)
    point P10 (167.8816, -195.5)
    point P11 (171.9231, -188.5)
    point P12 (167.8816, -181.5)
    point P13 (159.7987, -181.5)
    point P14 (155.7572, -188.5)
    point P15 (159.7987, -195.5)
    point P16 (169.9023, -192)
    line L8 (167.8816, -195.5) -> (171.9231, -188.5)
    line L9 (171.9231, -188.5) -> (167.8816, -181.5)
    line L10 (167.8816, -181.5) -> (159.7987, -181.5)
    line L11 (159.7987, -181.5) -> (155.7572, -188.5)
    line L12 (155.7572, -188.5) -> (159.7987, -195.5)
    line L13 (159.7987, -195.5) -> (167.8816, -195.5)
    construction line L14 (163.8401, -188.5) -> (169.9023, -192)
    construction circle A4 centre (163.8401, -188.5) radius 8.0829
    construction arc A5 centre (155.7572, -188.5) radius 8.0829 from (159.7987, -181.5) to (159.7987, -195.5) cw
    construction arc A6 centre (171.9231, -188.5) radius 8.0829 from (167.8816, -181.5) to (167.8816, -195.5) ccw
    reference projected point E1 (93.8401, -188.5) from axis of face of Pocket1 from Sketch5.A2
    reference projected point E2 (163.8401, -188.5) from axis of face of Pocket1 from Sketch5.A1
    reference intersected line E3 through (0, -177.5) direction (-1, 0) from face of Pad3
    distance L10 L13 = 14
    distance L3 L6 = 14
    coincidence: A1 P2, A1 P3, A1 P4, A1 P5, A1 P6, A1 P7, A2 P1, A3 P1, A4 P10, A4 P11, A4 P12, A4 P13, A4 P14, A4 P15, A5 P9, A6 P9, P1 E1, P9 E2
    midpoint: P8 L1, P16 L8
    parallelism: L1 L4, L8 L11, L3 L10, L3 E3
  Pad19: profile Sketch47, direction (0, 0, -1), length 6
  Sketch48 on end face of Pad19, origin (93.8401, 189.0774, -23), H (1, 0, 0), V (0, -1, 0)
    point P1 (0, 0.5774)
    reference projected point E1 (0, 0.5774) from axis of face of Pocket1 from Sketch5.A2
    coincidence: P1 E1
  Hole11: placed by Sketch48, at (93.8401, 188.5, -23) direction (0, 0, 1), diameter 6.647, through (limit type 3), threaded "M8", thread diameter 8, thread depth 6, pitch 1.25
  Sketch49 on end face of Pad19, origin (163.8401, 190.3666, -23), H (1, 0, 0), V (0, -1, 0)
    point P1 (0, 1.8666)
    reference projected point E1 (0, 1.8666) from axis of face of Pocket1 from Sketch5.A1
    coincidence: P1 E1
  Hole12: placed by Sketch49, at (163.8401, 188.5, -23) direction (0, 0, 1), diameter 6.647, through (limit type 3), threaded "M8", thread diameter 8, thread depth 6, pitch 1.25
  Plane5: type OffsetPt, RefPlane face of Pad19 from Sketch47.L10, RefPoint vertex [face of Pad19 from Sketch47.L9 | face of Pad19 from Sketch47.L8 | end face of Pad19]
  Sketch50 on Plane5, origin (0, 188.5, 0), H (-1, 0, 0), V (0, 0, 1)
    line L1 (-171.9231, -21.8) -> (-170.7231, -23)
    line L2 (-170.7231, -23) -> (-171.9231, -23)
    line L3 (-171.9231, -23) -> (-171.9231, -21.8)
    reference projected line E1 (-171.9231, -17) -> (-171.9231, -23) from edge [face of Pad19 from Sketch47.L9 | face of Pad19 from Sketch47.L8]
    reference intersected line E2 through (0, -23) direction (1, 0) from end face of Pad19
    length L3 = 1.2
    angle L1 L3 = 45
    horizontal: L2 H
    vertical: L3 V
    coincidence: L3 E1, L2 E2
  Groove1: profile Sketch50, axis axis of face of Hole12, angle 360
  Sketch51 on Plane5, origin (0, 188.5, 0), H (-1, 0, 0), V (0, 0, 1)
    line L1 (-101.9231, -21.8) -> (-100.7231, -23)
    line L2 (-100.7231, -23) -> (-101.9231, -23)
    line L3 (-101.9231, -23) -> (-101.9231, -21.8)
    reference projected line E1 (-101.9231, -17) -> (-101.9231, -23) from edge [face of Pad19 from Sketch47.L2 | face of Pad19 from Sketch47.L1]
    reference intersected line E2 through (0, -23) direction (1, 0) from end face of Pad19
    length L3 = 1.2
    angle L1 L3 = 45
    horizontal: L2 H
    vertical: L3 V
    coincidence: L3 E1, L2 E2
  Groove2: profile Sketch51, axis axis of face of Hole11, angle 360
Body11
  Plane6: type Offset, RefPlane YZ plane of AxisSystem1, Offset 130, reversed
  Sketch52 on Plane6, origin (-130, 0, 0), H (0, 1, 0), V (0, 0, 1)
    point P1 (-2.5, 25)
    line L1 (-2.5, 25) -> (-10.5, 25)
    line L2 (-12.5, 27) -> (-12.5, 75)
    point P2 (-12.5, 75)
    arc A1 centre (-10.5, 27) radius 2 from (-10.5, 25) to (-12.5, 27) cw
    reference intersected line E1 (-11, 25) -> (11, 25) from face of Pad1
    reference intersected line E2 (-12.5, -23.5) -> (-12.5, 23.5) from face of Pad1
    radius A1 = 2
    distance P1 L2 = 10
    distance P2 L1 = 50
    horizontal: L1 H
    vertical: L2 V
    tangency: A1 L1, A1 L2
    coincidence: L1 E1, L2 E2
  Pad20: profile Sketch52, direction (-1, 0, 0), length 71, thin wall 2
  Fillet7: radius 5, on edge [end face of Pad20 | face of Pad20]; edge [face of Pad20 | start face of Pad20]
  Sketch53 on face of Pad20, origin (0, -12.5, 0), H (1, 0, 0), V (0, 0, 1)
    line L1 (-182, 63) -> (-142, 63)
    line L2 (-142, 63) -> (-142, 35)
    line L3 (-142, 35) -> (-182, 35)
    line L4 (-189, 42) -> (-189, 56)
    reference intersected line E1 (-201, 75) -> (-130, 75) from face of Pad20
    reference intersected line E2 (-130, 75) -> (-130, 27) from start face of Pad20
    line L5 (-182, 63) -> (-189, 56)
    point P4 (-189, 56)
    line L6 (-182, 35) -> (-189, 42)
    point P6 (-189, 42)
    distance L1 L3 = 28
    distance L2 L4 = 47
    distance L1 E1 = 12
    distance L2 E2 = 12
    angle L1 L5 = 45
    angle L3 L6 = 45
    distance P4 L1 = 7
    distance P6 L3 = 7
    horizontal: L1 H, L3 H
    vertical: L2 V, L4 V
  Pocket18: profile Sketch53, direction (0, 1, 0), through (limit type 3)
